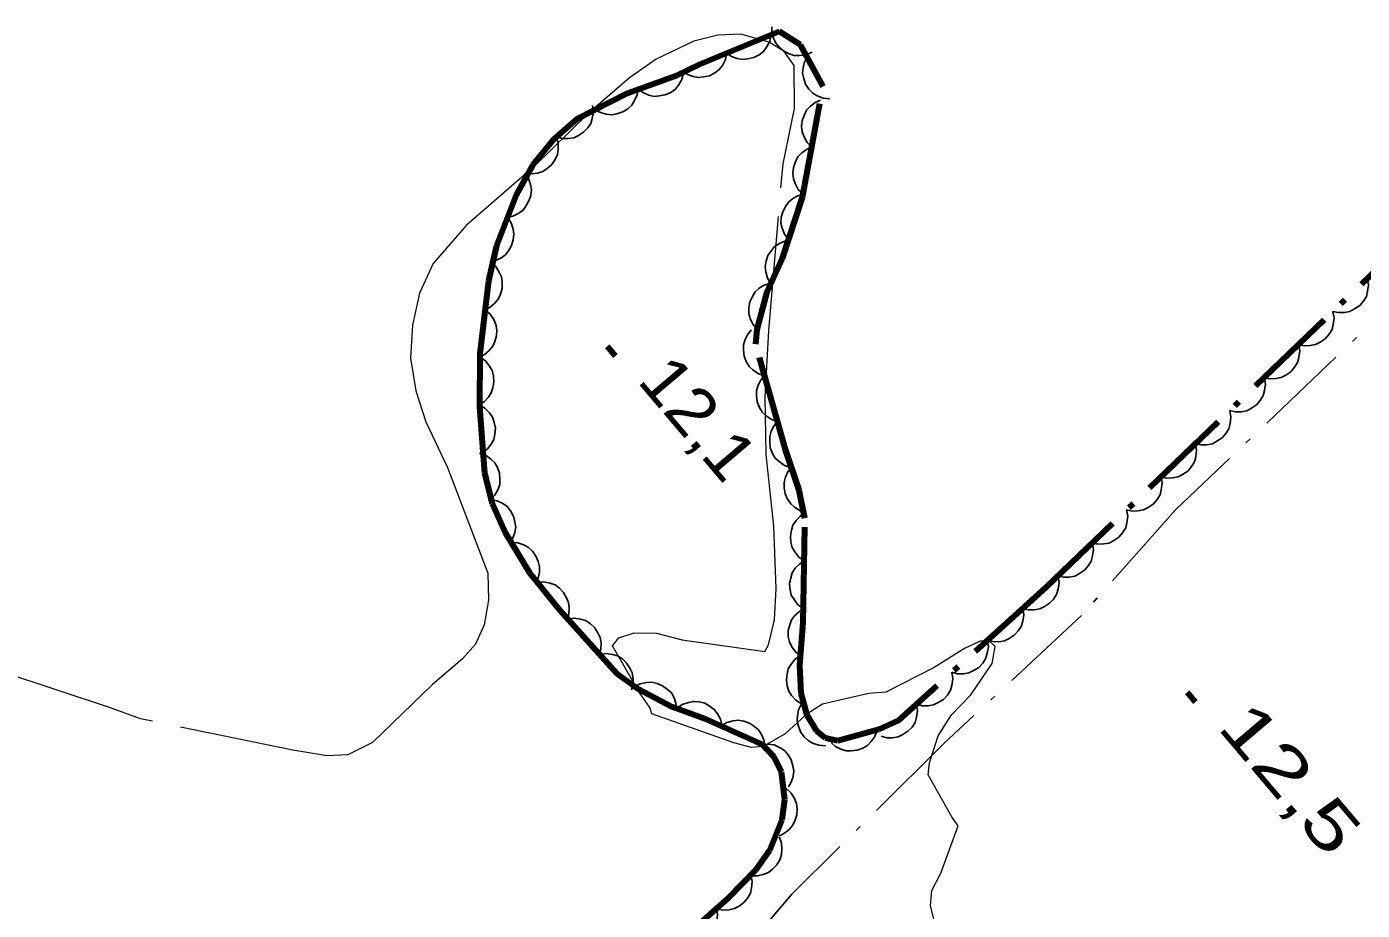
# Model space of a CAD drawing. Extents: x 386081 to 389416, y 5130568 to 5134082.
# Drawn here: x 387127.7 to 387211.7, y 5132452.2 to 5132507.7 of the extents above; entities that cross this region are included whole.
import ezdxf

# ---------------------------------------------------------------- set-up
doc = ezdxf.new("R2010")
doc.units = 0
doc.header["$LTSCALE"] = 1.2
doc.linetypes.add('DOT_DASHED', pattern=[7.7, 5, -1.2, 0.3, -1.2])
doc.linetypes.add('LONG_DASHED', pattern=[7.5, 6, -1.5])
for name, color, linetype, lineweight in [('2', 7, 'Continuous', 13), ('3', 7, 'Continuous', 140), ('41', 7, 'DOT_DASHED', 25), ('44', 7, 'Continuous', 25)]:
    doc.layers.add(name, color=color, linetype=linetype, lineweight=lineweight)

msp = doc.modelspace()

# ---------------------------------------------------------------- linework, layer by layer
at = {"layer": '2', "linetype": 'LONG_DASHED'}
msp.add_lwpolyline([(387166.99, 5132464.51), (387166.87, 5132464.92), (387166.19, 5132465.88), (387164.51, 5132468.8), (387164.91, 5132469.3), (387165.88, 5132469.61), (387167.28, 5132469.59), (387168.9, 5132469.17), (387174.09, 5132468.45), (387174.33, 5132468.86), (387174.71, 5132470.44), (387174.81, 5132472.4), (387174.66, 5132476.32), (387174.18, 5132480.83), (387174.12, 5132484.44), (387174.35, 5132488.63), (387175.24, 5132499.11), (387175.96, 5132502.59), (387175.95, 5132505.3), (387175.31, 5132506.18), (387174.37, 5132506.75), (387172.58, 5132507.26), (387171.14, 5132507.2), (387169.64, 5132506.82), (387167.27, 5132505.69), (387165.59, 5132504.51), (387162.97, 5132502.26), (387159.6, 5132498.93), (387155.34, 5132495.26), (387153.25, 5132492.84), (387152.39, 5132490.97), (387151.94, 5132488.97), (387151.83, 5132486.88), (387152.15, 5132484.84), (387152.79, 5132482.88), (387154.14, 5132480), (387156.69, 5132473.36), (387156.73, 5132471.67), (387156.45, 5132470.12), (387155.9, 5132468.91), (387155.08, 5132467.97), (387153.2, 5132466.37), (387149.44, 5132462.71), (387147.88, 5132461.95), (387146.56, 5132461.88), (387144.42, 5132462.24), (387134.84, 5132464.21), (387132.96, 5132464.9), (387124.85, 5132467.57)], dxfattribs=at)
at = {"layer": '2'}
msp.add_lwpolyline([(387185.16, 5132449.89), (387184.5, 5132452.44), (387184.6, 5132453.41), (387185.15, 5132454.5), (387186.24, 5132457.48), (387185.87, 5132458), (387184.36, 5132460.68), (387184.45, 5132461.44), (387184.99, 5132463.13), (387185.83, 5132464.46), (387187.04, 5132465.72), (387188.38, 5132467.68), (387188.57, 5132468.76), (387188.18, 5132469.13), (387187.64, 5132469.09), (387186.64, 5132468.63), (387184.74, 5132467.43), (387181.71, 5132465.88), (387180.63, 5132465.79), (387177.73, 5132465.12), (387176.67, 5132464.46), (387175.37, 5132463.26), (387174, 5132462.47), (387173.26, 5132462.41), (387172.15, 5132462.7), (387166.99, 5132464.51)], dxfattribs=at)
at = {"layer": '3'}
for p, q in [((387164.18, 5132487.65), (387164.69, 5132487.04)), ((387200.64, 5132465.88), (387201.15, 5132465.27))]:
    msp.add_line(p, q, dxfattribs=at)
at = {"layer": '41'}
msp.add_lwpolyline([(387216.69, 5132493.31), (387199.93, 5132477.37), (387194.01, 5132470.7), (387185.37, 5132462.67), (387175.79, 5132453.18), (387172.06, 5132448.79), (387171.05, 5132446.32), (387170.42, 5132444.47), (387170.28, 5132442.37), (387170.21, 5132439.36), (387170.82, 5132437.5), (387171.68, 5132435.64), (387172.55, 5132434.53), (387173.73, 5132432.99), (387174.84, 5132431.62), (387179.79, 5132426.9), (387195.16, 5132415.68), (387201.97, 5132410.58), (387205.69, 5132408.08), (387209.75, 5132406.15), (387211.86, 5132405.52)], dxfattribs=at)
at = {"layer": '44'}
for points in [[(387177.07, 5132506.13), (387176.69, 5132505.96), (387176.28, 5132505.91), (387175.95, 5132505.92), (387175.62, 5132506.02), (387175.29, 5132506.19), (387175, 5132506.45), (387174.78, 5132506.69), (387174.64, 5132507.01), (387174.54, 5132507.37), (387174.53, 5132507.73)], [(387174.48, 5132507.2), (387174.4, 5132506.79), (387174.2, 5132506.44), (387174.01, 5132506.17), (387173.73, 5132505.96), (387173.4, 5132505.79), (387173.02, 5132505.7), (387172.7, 5132505.67), (387172.36, 5132505.73), (387172.01, 5132505.86), (387171.71, 5132506.06)], [(387171.71, 5132506.06), (387171.62, 5132505.66), (387171.43, 5132505.3), (387171.23, 5132505.03), (387170.95, 5132504.82), (387170.62, 5132504.65), (387170.25, 5132504.57), (387169.92, 5132504.53), (387169.58, 5132504.6), (387169.23, 5132504.73), (387168.93, 5132504.93)], [(387178.19, 5132503.2), (387177.77, 5132503.24), (387177.39, 5132503.39), (387177.11, 5132503.56), (387176.87, 5132503.81), (387176.66, 5132504.12), (387176.54, 5132504.48), (387176.47, 5132504.8), (387176.5, 5132505.15), (387176.59, 5132505.51), (387176.75, 5132505.83)], [(387168.98, 5132504.81), (387168.88, 5132504.41), (387168.67, 5132504.06), (387168.47, 5132503.8), (387168.18, 5132503.6), (387167.84, 5132503.44), (387167.47, 5132503.38), (387167.14, 5132503.35), (387166.8, 5132503.43), (387166.46, 5132503.58), (387166.16, 5132503.79)], [(387166.13, 5132503.86), (387166.08, 5132503.45), (387165.91, 5132503.08), (387165.74, 5132502.8), (387165.48, 5132502.56), (387165.16, 5132502.37), (387164.8, 5132502.25), (387164.48, 5132502.19), (387164.13, 5132502.23), (387163.77, 5132502.33), (387163.45, 5132502.51)], [(387163.27, 5132502.78), (387163.32, 5132502.36), (387163.25, 5132501.96), (387163.16, 5132501.65), (387162.96, 5132501.36), (387162.7, 5132501.09), (387162.38, 5132500.89), (387162.08, 5132500.75), (387161.73, 5132500.7), (387161.36, 5132500.71), (387161.01, 5132500.8)], [(387177.05, 5132500.15), (387176.75, 5132500.45), (387176.56, 5132500.81), (387176.44, 5132501.11), (387176.41, 5132501.47), (387176.45, 5132501.83), (387176.58, 5132502.19), (387176.72, 5132502.49), (387176.97, 5132502.74), (387177.27, 5132502.96), (387177.6, 5132503.1)], [(387160.98, 5132500.83), (387161.1, 5132500.43), (387161.1, 5132500.02), (387161.06, 5132499.7), (387160.91, 5132499.38), (387160.7, 5132499.07), (387160.41, 5132498.82), (387160.15, 5132498.63), (387159.81, 5132498.53), (387159.44, 5132498.48), (387159.08, 5132498.51)], [(387176.5, 5132497.21), (387176.2, 5132497.5), (387176.01, 5132497.86), (387175.89, 5132498.17), (387175.86, 5132498.52), (387175.9, 5132498.88), (387176.03, 5132499.24), (387176.18, 5132499.54), (387176.42, 5132499.79), (387176.72, 5132500.01), (387177.05, 5132500.15)], [(387159, 5132498.53), (387159.24, 5132498.18), (387159.36, 5132497.8), (387159.42, 5132497.47), (387159.38, 5132497.12), (387159.27, 5132496.77), (387159.08, 5132496.44), (387158.88, 5132496.18), (387158.59, 5132495.98), (387158.26, 5132495.81), (387157.91, 5132495.73)], [(387175.59, 5132494.35), (387175.33, 5132494.68), (387175.19, 5132495.06), (387175.11, 5132495.38), (387175.13, 5132495.73), (387175.22, 5132496.09), (387175.4, 5132496.43), (387175.58, 5132496.7), (387175.85, 5132496.92), (387176.18, 5132497.1), (387176.53, 5132497.2)], [(387157.91, 5132495.73), (387158.14, 5132495.39), (387158.27, 5132495), (387158.32, 5132494.68), (387158.28, 5132494.33), (387158.18, 5132493.97), (387157.98, 5132493.64), (387157.79, 5132493.38), (387157.5, 5132493.18), (387157.16, 5132493.02), (387156.81, 5132492.94)], [(387174.48, 5132491.56), (387174.26, 5132491.92), (387174.16, 5132492.31), (387174.11, 5132492.64), (387174.17, 5132492.99), (387174.29, 5132493.34), (387174.51, 5132493.66), (387174.71, 5132493.91), (387175.01, 5132494.09), (387175.35, 5132494.24), (387175.71, 5132494.3)], [(387156.87, 5132492.91), (387157.18, 5132492.64), (387157.4, 5132492.29), (387157.54, 5132491.99), (387157.59, 5132491.64), (387157.58, 5132491.27), (387157.47, 5132490.91), (387157.34, 5132490.6), (387157.12, 5132490.34), (387156.83, 5132490.1), (387156.51, 5132489.93)], [(387173.61, 5132488.7), (387173.34, 5132489.02), (387173.18, 5132489.39), (387173.08, 5132489.7), (387173.09, 5132490.06), (387173.15, 5132490.42), (387173.31, 5132490.77), (387173.48, 5132491.05), (387173.74, 5132491.28), (387174.06, 5132491.48), (387174.4, 5132491.59)], [(387211.97, 5132491.91), (387212.05, 5132491.49), (387211.99, 5132491.09), (387211.91, 5132490.77), (387211.73, 5132490.47), (387211.49, 5132490.19), (387211.17, 5132489.98), (387210.88, 5132489.82), (387210.53, 5132489.76), (387210.16, 5132489.75), (387209.81, 5132489.83)], [(387156.51, 5132489.93), (387156.83, 5132489.66), (387157.05, 5132489.31), (387157.19, 5132489.01), (387157.24, 5132488.66), (387157.22, 5132488.29), (387157.12, 5132487.93), (387156.99, 5132487.63), (387156.76, 5132487.36), (387156.48, 5132487.12), (387156.16, 5132486.95)], [(387209.81, 5132489.83), (387209.88, 5132489.42), (387209.83, 5132489.01), (387209.75, 5132488.69), (387209.57, 5132488.39), (387209.32, 5132488.11), (387209.01, 5132487.9), (387208.72, 5132487.74), (387208.37, 5132487.68), (387208, 5132487.67), (387207.65, 5132487.75)], [(387174.08, 5132485.78), (387173.69, 5132485.91), (387173.35, 5132486.15), (387173.11, 5132486.37), (387172.93, 5132486.67), (387172.8, 5132487.02), (387172.76, 5132487.4), (387172.76, 5132487.73), (387172.86, 5132488.06), (387173.03, 5132488.39), (387173.26, 5132488.67)], [(387207.65, 5132487.75), (387207.72, 5132487.34), (387207.67, 5132486.93), (387207.59, 5132486.61), (387207.4, 5132486.31), (387207.16, 5132486.03), (387206.84, 5132485.82), (387206.56, 5132485.66), (387206.21, 5132485.6), (387205.84, 5132485.59), (387205.49, 5132485.67)], [(387156.19, 5132486.95), (387156.53, 5132486.71), (387156.78, 5132486.39), (387156.95, 5132486.11), (387157.04, 5132485.77), (387157.06, 5132485.4), (387157, 5132485.02), (387156.9, 5132484.71), (387156.71, 5132484.42), (387156.45, 5132484.15), (387156.15, 5132483.95)], [(387174.9, 5132482.9), (387174.51, 5132483.03), (387174.17, 5132483.26), (387173.93, 5132483.49), (387173.75, 5132483.79), (387173.62, 5132484.13), (387173.58, 5132484.51), (387173.58, 5132484.84), (387173.68, 5132485.18), (387173.85, 5132485.51), (387174.08, 5132485.78)], [(387205.49, 5132485.67), (387205.56, 5132485.26), (387205.51, 5132484.85), (387205.42, 5132484.53), (387205.24, 5132484.23), (387205, 5132483.95), (387204.68, 5132483.74), (387204.4, 5132483.58), (387204.05, 5132483.52), (387203.68, 5132483.51), (387203.33, 5132483.59)], [(387156.14, 5132483.95), (387156.5, 5132483.74), (387156.78, 5132483.45), (387156.98, 5132483.18), (387157.09, 5132482.85), (387157.16, 5132482.48), (387157.12, 5132482.1), (387157.06, 5132481.78), (387156.89, 5132481.47), (387156.66, 5132481.18), (387156.38, 5132480.96)], [(387203.33, 5132483.59), (387203.4, 5132483.18), (387203.35, 5132482.77), (387203.26, 5132482.45), (387203.08, 5132482.15), (387202.84, 5132481.87), (387202.52, 5132481.66), (387202.23, 5132481.5), (387201.89, 5132481.44), (387201.52, 5132481.43), (387201.16, 5132481.51)], [(387175.72, 5132480.01), (387175.33, 5132480.14), (387174.99, 5132480.38), (387174.75, 5132480.6), (387174.57, 5132480.9), (387174.44, 5132481.25), (387174.4, 5132481.63), (387174.4, 5132481.95), (387174.5, 5132482.29), (387174.67, 5132482.62), (387174.9, 5132482.9)], [(387201.16, 5132481.51), (387201.24, 5132481.1), (387201.18, 5132480.69), (387201.1, 5132480.37), (387200.92, 5132480.07), (387200.68, 5132479.79), (387200.36, 5132479.58), (387200.07, 5132479.42), (387199.72, 5132479.36), (387199.35, 5132479.35), (387199, 5132479.43)], [(387156.16, 5132480.92), (387156.56, 5132480.78), (387156.88, 5132480.54), (387157.12, 5132480.3), (387157.29, 5132480), (387157.41, 5132479.65), (387157.44, 5132479.26), (387157.43, 5132478.94), (387157.31, 5132478.61), (387157.13, 5132478.28), (387156.89, 5132478.01)], [(387176.71, 5132477.18), (387176.31, 5132477.29), (387175.97, 5132477.51), (387175.72, 5132477.72), (387175.53, 5132478.02), (387175.38, 5132478.36), (387175.32, 5132478.74), (387175.31, 5132479.06), (387175.4, 5132479.4), (387175.55, 5132479.74), (387175.77, 5132480.03)], [(387199, 5132479.43), (387199.07, 5132479.02), (387199.02, 5132478.61), (387198.94, 5132478.29), (387198.76, 5132477.99), (387198.51, 5132477.71), (387198.2, 5132477.5), (387197.91, 5132477.34), (387197.56, 5132477.28), (387197.19, 5132477.27), (387196.84, 5132477.35)], [(387156.85, 5132478), (387157.26, 5132477.92), (387157.62, 5132477.74), (387157.89, 5132477.55), (387158.11, 5132477.28), (387158.29, 5132476.96), (387158.39, 5132476.59), (387158.44, 5132476.26), (387158.38, 5132475.92), (387158.26, 5132475.56), (387158.07, 5132475.26)], [(387196.84, 5132477.35), (387196.91, 5132476.94), (387196.86, 5132476.53), (387196.78, 5132476.21), (387196.59, 5132475.91), (387196.35, 5132475.63), (387196.03, 5132475.42), (387195.75, 5132475.26), (387195.4, 5132475.2), (387195.03, 5132475.19), (387194.68, 5132475.27)], [(387176.57, 5132474.14), (387176.23, 5132474.38), (387175.98, 5132474.7), (387175.81, 5132474.98), (387175.72, 5132475.32), (387175.7, 5132475.69), (387175.77, 5132476.07), (387175.86, 5132476.38), (387176.06, 5132476.67), (387176.31, 5132476.94), (387176.61, 5132477.14)], [(387158.15, 5132475.3), (387158.57, 5132475.28), (387158.95, 5132475.14), (387159.24, 5132474.99), (387159.5, 5132474.74), (387159.71, 5132474.44), (387159.85, 5132474.09), (387159.94, 5132473.77), (387159.93, 5132473.42), (387159.85, 5132473.06), (387159.7, 5132472.73)], [(387194.68, 5132475.27), (387194.75, 5132474.86), (387194.7, 5132474.45), (387194.62, 5132474.13), (387194.43, 5132473.83), (387194.19, 5132473.55), (387193.87, 5132473.34), (387193.59, 5132473.18), (387193.24, 5132473.12), (387192.87, 5132473.11), (387192.52, 5132473.19)], [(387176.52, 5132471.14), (387176.18, 5132471.38), (387175.93, 5132471.7), (387175.76, 5132471.98), (387175.68, 5132472.32), (387175.65, 5132472.69), (387175.72, 5132473.07), (387175.81, 5132473.38), (387176.01, 5132473.67), (387176.27, 5132473.94), (387176.57, 5132474.14)], [(387192.54, 5132473.16), (387192.6, 5132472.75), (387192.53, 5132472.35), (387192.44, 5132472.03), (387192.25, 5132471.74), (387192, 5132471.47), (387191.67, 5132471.26), (387191.38, 5132471.12), (387191.03, 5132471.06), (387190.66, 5132471.07), (387190.31, 5132471.15)], [(387159.78, 5132472.79), (387160.2, 5132472.82), (387160.59, 5132472.74), (387160.91, 5132472.63), (387161.19, 5132472.42), (387161.44, 5132472.15), (387161.63, 5132471.82), (387161.76, 5132471.52), (387161.79, 5132471.17), (387161.77, 5132470.8), (387161.66, 5132470.45)], [(387161.7, 5132470.48), (387162.11, 5132470.54), (387162.51, 5132470.48), (387162.83, 5132470.38), (387163.12, 5132470.19), (387163.39, 5132469.94), (387163.6, 5132469.62), (387163.75, 5132469.32), (387163.8, 5132468.98), (387163.79, 5132468.61), (387163.71, 5132468.26)], [(387176.35, 5132468.15), (387176.02, 5132468.41), (387175.79, 5132468.74), (387175.64, 5132469.04), (387175.57, 5132469.38), (387175.57, 5132469.75), (387175.66, 5132470.12), (387175.78, 5132470.43), (387175.99, 5132470.71), (387176.27, 5132470.96), (387176.58, 5132471.14)], [(387190.31, 5132471.15), (387190.37, 5132470.74), (387190.31, 5132470.34), (387190.21, 5132470.02), (387190.02, 5132469.73), (387189.77, 5132469.46), (387189.45, 5132469.25), (387189.16, 5132469.1), (387188.81, 5132469.05), (387188.44, 5132469.06), (387188.09, 5132469.14)], [(387188.09, 5132469.14), (387188.15, 5132468.73), (387188.08, 5132468.33), (387187.99, 5132468.01), (387187.8, 5132467.71), (387187.55, 5132467.44), (387187.22, 5132467.24), (387186.93, 5132467.09), (387186.58, 5132467.04), (387186.21, 5132467.04), (387185.86, 5132467.13)], [(387163.71, 5132468.26), (387164.12, 5132468.31), (387164.52, 5132468.25), (387164.84, 5132468.16), (387165.14, 5132467.97), (387165.41, 5132467.71), (387165.61, 5132467.39), (387165.76, 5132467.1), (387165.81, 5132466.75), (387165.81, 5132466.38), (387165.72, 5132466.03)], [(387176.41, 5132465.15), (387176.05, 5132465.37), (387175.78, 5132465.67), (387175.6, 5132465.95), (387175.49, 5132466.28), (387175.45, 5132466.65), (387175.49, 5132467.03), (387175.57, 5132467.35), (387175.75, 5132467.65), (387175.99, 5132467.93), (387176.27, 5132468.15)], [(387185.86, 5132467.13), (387185.92, 5132466.72), (387185.86, 5132466.31), (387185.76, 5132466), (387185.57, 5132465.7), (387185.32, 5132465.43), (387185, 5132465.23), (387184.7, 5132465.08), (387184.36, 5132465.03), (387183.99, 5132465.03), (387183.64, 5132465.12)], [(387165.89, 5132466.21), (387166.26, 5132466.41), (387166.66, 5132466.49), (387166.99, 5132466.51), (387167.33, 5132466.43), (387167.67, 5132466.29), (387167.98, 5132466.06), (387168.22, 5132465.83), (387168.39, 5132465.53), (387168.51, 5132465.18), (387168.55, 5132464.82)], [(387168.57, 5132464.86), (387168.9, 5132465.1), (387169.29, 5132465.24), (387169.61, 5132465.3), (387169.96, 5132465.27), (387170.32, 5132465.18), (387170.65, 5132464.99), (387170.92, 5132464.8), (387171.13, 5132464.51), (387171.3, 5132464.19), (387171.39, 5132463.84)], [(387177.9, 5132462.51), (387177.48, 5132462.54), (387177.1, 5132462.68), (387176.81, 5132462.84), (387176.56, 5132463.08), (387176.34, 5132463.38), (387176.21, 5132463.74), (387176.12, 5132464.06), (387176.14, 5132464.41), (387176.22, 5132464.77), (387176.37, 5132465.1)], [(387183.64, 5132465.12), (387183.69, 5132464.7), (387183.63, 5132464.3), (387183.54, 5132463.98), (387183.35, 5132463.69), (387183.09, 5132463.42), (387182.77, 5132463.21), (387182.48, 5132463.07), (387182.13, 5132463.02), (387181.76, 5132463.02), (387181.41, 5132463.11)], [(387171.36, 5132463.76), (387171.71, 5132463.98), (387172.11, 5132464.08), (387172.43, 5132464.12), (387172.78, 5132464.06), (387173.13, 5132463.94), (387173.45, 5132463.73), (387173.7, 5132463.52), (387173.89, 5132463.22), (387174.03, 5132462.88), (387174.09, 5132462.52)], [(387181.16, 5132463.5), (387181.02, 5132463.1), (387180.79, 5132462.77), (387180.56, 5132462.53), (387180.26, 5132462.36), (387179.91, 5132462.23), (387179.53, 5132462.19), (387179.2, 5132462.19), (387178.87, 5132462.3), (387178.54, 5132462.47), (387178.26, 5132462.71)], [(387174.27, 5132462.62), (387174.69, 5132462.56), (387175.05, 5132462.39), (387175.33, 5132462.21), (387175.56, 5132461.94), (387175.75, 5132461.62), (387175.86, 5132461.25), (387175.92, 5132460.93), (387175.87, 5132460.58), (387175.76, 5132460.23), (387175.58, 5132459.92)], [(387175.44, 5132459.82), (387175.75, 5132459.54), (387175.96, 5132459.19), (387176.09, 5132458.89), (387176.13, 5132458.54), (387176.11, 5132458.17), (387175.99, 5132457.8), (387175.86, 5132457.51), (387175.63, 5132457.24), (387175.34, 5132457.01), (387175.02, 5132456.85)], [(387175, 5132456.79), (387175.14, 5132456.4), (387175.17, 5132456), (387175.15, 5132455.67), (387175.03, 5132455.34), (387174.84, 5132455.02), (387174.57, 5132454.75), (387174.32, 5132454.54), (387173.99, 5132454.41), (387173.63, 5132454.34), (387173.27, 5132454.34)], [(387173.22, 5132454.39), (387173.3, 5132453.98), (387173.26, 5132453.57), (387173.19, 5132453.25), (387173.02, 5132452.94), (387172.78, 5132452.66), (387172.48, 5132452.43), (387172.19, 5132452.27), (387171.85, 5132452.19), (387171.48, 5132452.17), (387171.12, 5132452.23)], [(387171.08, 5132452.28), (387171.13, 5132451.87), (387171.07, 5132451.47), (387170.97, 5132451.15), (387170.78, 5132450.86), (387170.53, 5132450.59), (387170.2, 5132450.39), (387169.91, 5132450.24), (387169.56, 5132450.19), (387169.19, 5132450.2), (387168.84, 5132450.29)]]:
    msp.add_lwpolyline(points, dxfattribs=at)
at = {"layer": '44', "linetype": 'DOT_DASHED', "lineweight": 90}
msp.add_lwpolyline([(387222.58, 5132502.11), (387191.77, 5132472.47), (387182.5, 5132464.09), (387181.27, 5132463.53), (387178.68, 5132462.82), (387177.91, 5132462.99), (387177.36, 5132463.42), (387176.76, 5132464.44), (387176.38, 5132465.82), (387176.3, 5132467.57), (387176.51, 5132470.26), (387176.61, 5132476.82), (387176.25, 5132478.58), (387175.4, 5132481.15), (387173.52, 5132487.76), (387173.61, 5132488.69), (387174.25, 5132491.05), (387175.2, 5132493.17), (387176.46, 5132497), (387177.76, 5132503.98), (387176.34, 5132506.59), (387175.02, 5132507.42), (387169.94, 5132505.34), (387168.56, 5132504.66), (387165.49, 5132503.54), (387162.28, 5132501.91), (387160.82, 5132500.63), (387159.52, 5132499.04), (387158.46, 5132497.15), (387157.22, 5132493.98), (387156.73, 5132491.75), (387156.19, 5132487.18), (387156.15, 5132483.83), (387156.48, 5132479.66), (387156.96, 5132477.74), (387157.77, 5132475.93), (387159.32, 5132473.36), (387161.18, 5132471.05), (387164.8, 5132467.05), (387166.13, 5132466.09), (387168.28, 5132464.96), (387170.41, 5132464.19), (387173.9, 5132462.61), (387174.66, 5132461.82), (387175.12, 5132460.87), (387175.34, 5132459.13), (387175.16, 5132457.86), (387174.38, 5132455.92), (387173.52, 5132454.7), (387171.8, 5132452.93), (387168.53, 5132450.01)], dxfattribs=at)

# ---------------------------------------------------------------- texts
at = {"layer": '3'}
for s, width, p in [('12,1   ', 1.1, (387166.01, 5132485.43)), ('12,5   ', 1.4, (387202.47, 5132463.66))]:
    msp.add_text(s, height=3, rotation=310.294, dxfattribs=dict(at, width=width)).set_placement(p)

doc.saveas('drawing.dxf')
